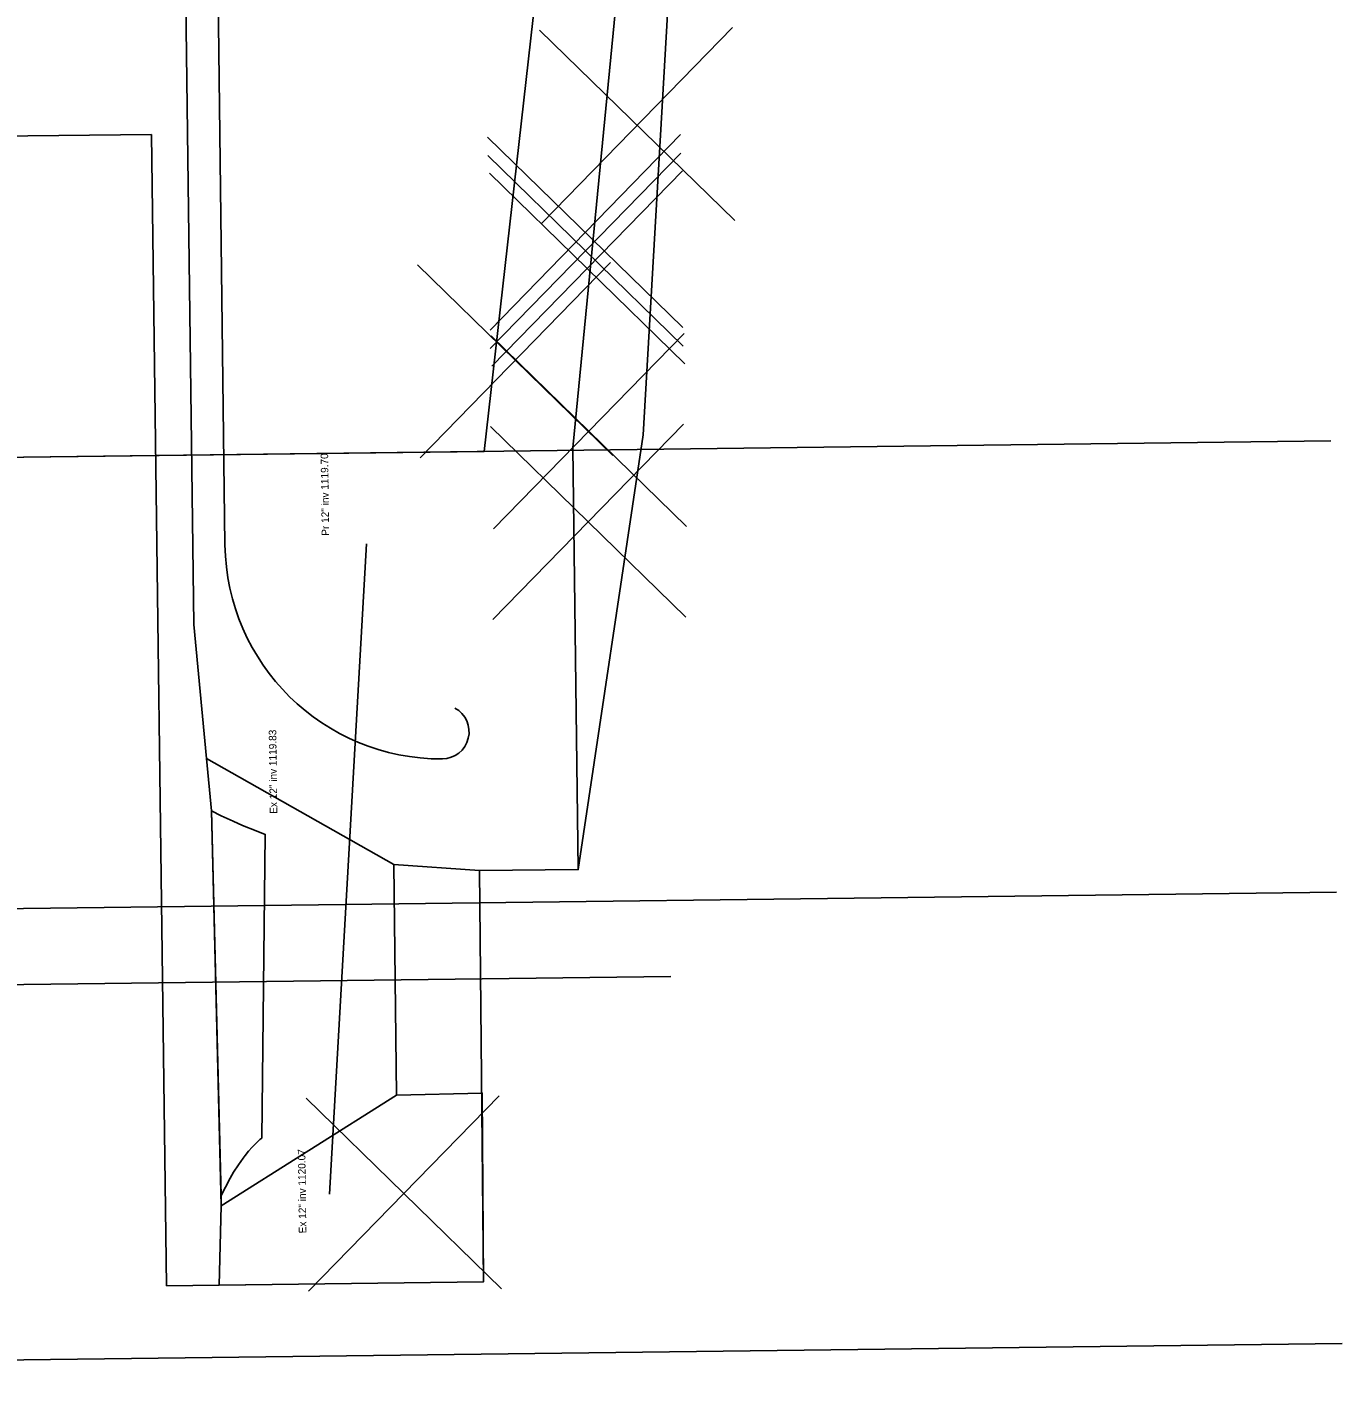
# Model space of a CAD drawing. Extents: x 2341000 to 2341204, y 624110 to 624511.
# Drawn here: x 2341129.8 to 2341202.7, y 624209.6 to 624284.3 of the extents above; entities that cross this region are included whole.
import ezdxf

# ---------------------------------------------------------------- set-up
doc = ezdxf.new("R2010")
doc.units = 0
for name, color, linetype in [('GE_P_Driveway_CL', 7, 'Continuous'), ('PV_P_Drive', 7, 'Continuous'), ('RD_P_GR_Lt', 7, 'Continuous'), ('RD_P_GR_Rt', 7, 'Continuous'), ('RW_P_Const_Limits', 7, 'Continuous'), ('SC_Scratch1', 7, 'Continuous'), ('SC_Scratch10', 7, 'Continuous'), ('SC_Scratch2', 7, 'Continuous'), ('SC_Scratch5', 7, 'Continuous'), ('SC_Scratch6', 7, 'Continuous'), ('VG_P_Cells', 7, 'Continuous')]:
    doc.layers.add(name, color=color, linetype=linetype)

msp = doc.modelspace()

# ---------------------------------------------------------------- linework, layer by layer
at = {"layer": 'GE_P_Driveway_CL'}
msp.add_line((2341165.46, 624231.741), (2341127.401, 624231.271), dxfattribs=at)
at = {"layer": 'PV_P_Drive'}
for p, q in [((2341150.108, 624237.948), (2341139.726, 624243.82)), ((2341150.266, 624225.157), (2341150.108, 624237.948)), ((2341140.537, 624219.036), (2341150.266, 624225.157))]:
    msp.add_line(p, q, dxfattribs=at)
msp.add_lwpolyline([(2341140.537, 624219.036), (2341140.55, 624219.6), (2341140, 624240.91), (2341139.726, 624243.82)], dxfattribs=at)
at = {"layer": 'RD_P_GR_Lt'}
msp.add_arc((2341152.751, 624255.79), 12, 180.69994, 270.2246, dxfattribs=at)
at = {"layer": 'RD_P_GR_Rt'}
msp.add_line((2341140.752, 624255.643), (2341138.462, 624443.129), dxfattribs=at)
msp.add_arc((2341152.78, 624245.29), 1.5, 270.70792, 61.59349, dxfattribs=at)
at = {"layer": 'RW_P_Const_Limits'}
for p, q in [((2341163.92, 624261.733), (2341165.918, 624296.352)), ((2341136.675, 624278.386), (2341115.404, 624278.123)), ((2341137.509, 624214.6), (2341136.675, 624278.386)), ((2341160.332, 624237.661), (2341163.92, 624261.733))]:
    msp.add_line(p, q, dxfattribs=at)
msp.add_lwpolyline([(2341160.332, 624237.661), (2341154.862, 624237.617), (2341155.07, 624214.817), (2341137.509, 624214.6)], dxfattribs=at)
at = {"layer": 'SC_Scratch1'}
for p, q in [((2341202.034, 624261.401), (2341052.046, 624259.548)), ((2341202.343, 624236.403), (2341052.355, 624234.55)), ((2341202.652, 624211.405), (2341052.663, 624209.551))]:
    msp.add_line(p, q, dxfattribs=at)
at = {"layer": 'SC_Scratch10'}
msp.add_lwpolyline([(2341163.501, 624296.736), (2341160.036, 624261.015), (2341160.332, 624237.661), (2341154.862, 624237.617), (2341150.108, 624237.948), (2341150.266, 624225.157), (2341155.006, 624225.275), (2341155.07, 624214.817), (2341140.437, 624214.636), (2341140.537, 624219.036), (2341140, 624240.91), (2341139.726, 624243.82), (2341139.03, 624251.23), (2341138.411, 624298.618)], dxfattribs=at)
at = {"layer": 'SC_Scratch2'}
msp.add_line((2341155.108, 624260.821), (2341083.683, 624259.939), dxfattribs=at)
for points in [[(2341155.108, 624260.821), (2341157.949, 624285.858), (2341158.378, 624298.864), (2341164.962, 624309.947), (2341158.941, 624318.873), (2341165.579, 624327.956), (2341162.383, 624338.917), (2341159.542, 624360.884), (2341158.213, 624385.869), (2341157.544, 624410.863), (2341158.375, 624435.875), (2341158.097, 624458.4)], [(2341155.108, 624260.821), (2341157.949, 624285.858), (2341158.378, 624298.864), (2341164.962, 624309.947), (2341158.941, 624318.873), (2341165.579, 624327.956), (2341162.383, 624338.917), (2341159.542, 624360.884), (2341158.213, 624385.869), (2341157.544, 624410.863), (2341158.375, 624435.875)]]:
    msp.add_lwpolyline(points, dxfattribs=at)
at = {"layer": 'SC_Scratch5'}
msp.add_lwpolyline([(2341142.79, 624222.79), (2341142.69, 624222.702), (2341142.516, 624222.54), (2341142.255, 624222.274), (2341142.063, 624222.06), (2341141.874, 624221.83), (2341141.753, 624221.672), (2341141.495, 624221.311), (2341141.227, 624220.891), (2341141.032, 624220.557), (2341140.775, 624220.07), (2341140.55, 624219.6), (2341140, 624240.91), (2341140.545, 624240.64), (2341141.202, 624240.334), (2341141.715, 624240.109), (2341142.472, 624239.8), (2341142.98, 624239.61)], close=True, dxfattribs=at)
at = {"layer": 'SC_Scratch6'}
msp.add_line((2341146.544, 624219.678), (2341148.599, 624255.706), dxfattribs=at)
at = {"layer": 'VG_P_Cells'}
for p, q in [((2341158.181, 624284.167), (2341169.004, 624273.608)), ((2341158.313, 624273.476), (2341168.872, 624284.299)), ((2341163.592, 624278.886), (2341163.592, 624278.886)), ((2341155.307, 624278.24), (2341166.13, 624267.681)), ((2341155.439, 624267.549), (2341165.998, 624278.372)), ((2341155.32, 624277.217), (2341166.143, 624266.658)), ((2341155.452, 624266.526), (2341166.011, 624277.349)), ((2341155.546, 624265.546), (2341166.105, 624276.369)), ((2341155.414, 624276.236), (2341166.237, 624265.678)), ((2341160.718, 624272.96), (2341160.718, 624272.96)), ((2341160.73, 624271.937), (2341160.73, 624271.937)), ((2341151.429, 624271.16), (2341162.252, 624260.602)), ((2341151.562, 624260.469), (2341162.12, 624271.292)), ((2341160.824, 624270.956), (2341160.824, 624270.956)), ((2341155.637, 624256.526), (2341166.196, 624267.349)), ((2341155.505, 624267.217), (2341166.328, 624256.658)), ((2341156.84, 624265.88), (2341156.84, 624265.88)), ((2341155.464, 624262.204), (2341166.287, 624251.646)), ((2341155.596, 624251.513), (2341166.155, 624262.336)), ((2341160.916, 624261.937), (2341160.916, 624261.937)), ((2341160.875, 624256.924), (2341160.875, 624256.924)), ((2341145.247, 624225.001), (2341156.07, 624214.442)), ((2341145.379, 624214.31), (2341155.938, 624225.133)), ((2341150.658, 624219.721), (2341150.658, 624219.721))]:
    msp.add_line(p, q, dxfattribs=at)

# ---------------------------------------------------------------- texts
at = {"layer": 'SC_Scratch1'}
for s, p in [('Pr 12" inv 1119.70', (2341146.526, 624256.154)), ('Ex 12" inv 1119.83', (2341143.652, 624240.752)), ('Ex 12" inv 1120.07', (2341145.263, 624217.513))]:
    msp.add_text(s, height=0.41667, rotation=90.70792, dxfattribs=at).set_placement(p)

doc.saveas('drawing.dxf')
